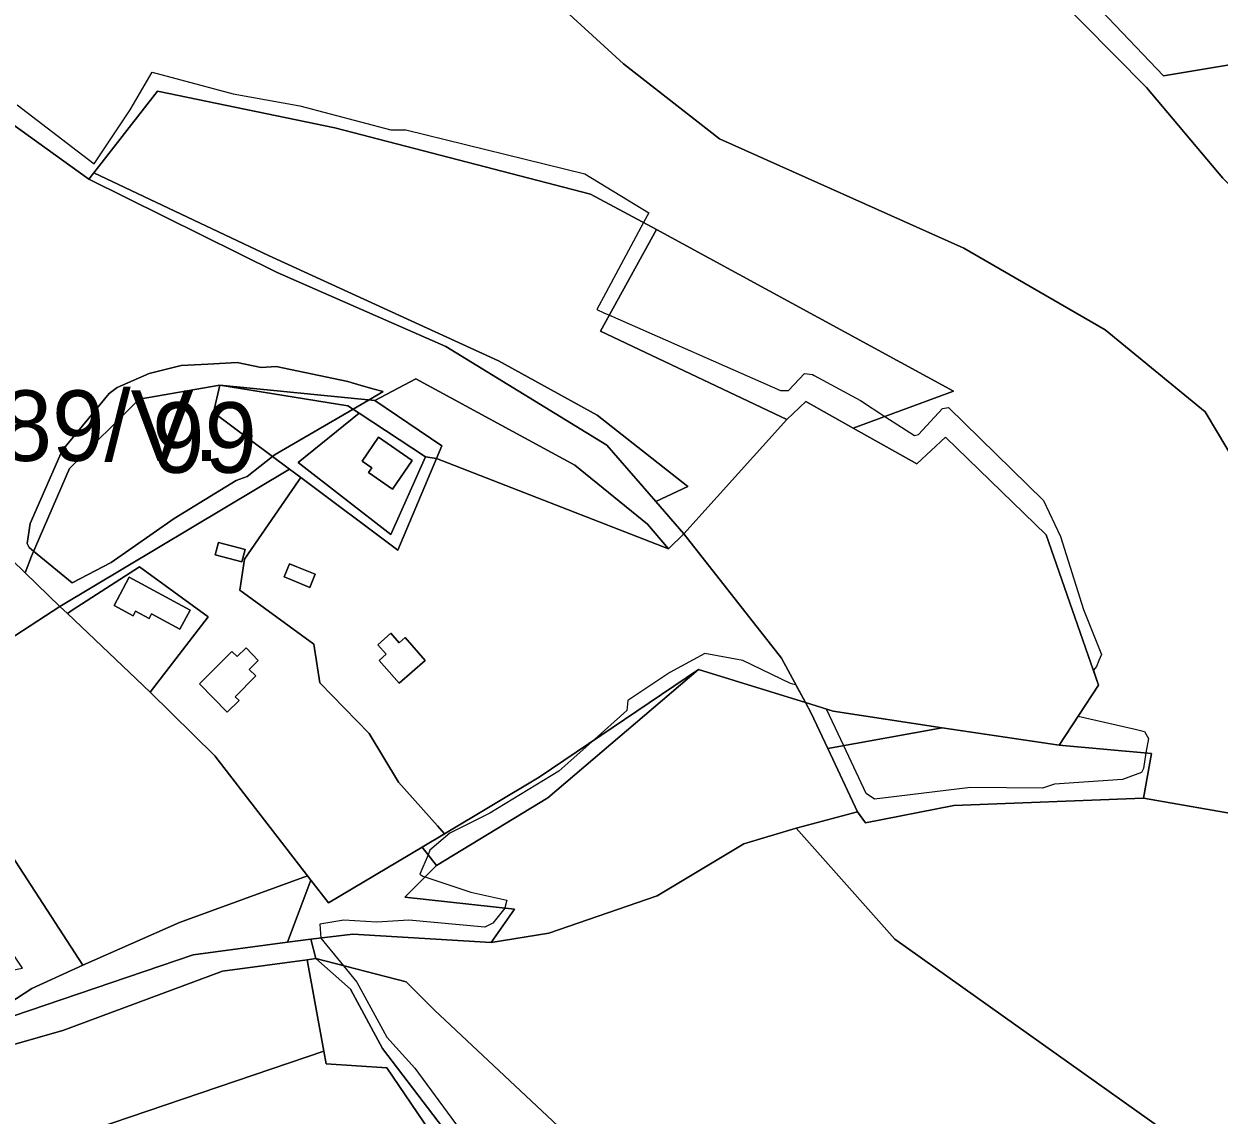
# Model space of a CAD drawing. Extents: x -477304 to -465429, y -1159113 to -1149210.
# Drawn here: x -474554.2 to -474299.9, y -1154850.7 to -1154618.5 of the extents above; entities that cross this region are included whole.
import ezdxf

# ---------------------------------------------------------------- set-up
doc = ezdxf.new("R2010")
doc.units = 0
for name, color, linetype in [('BPEJ_s', 7, 'Continuous'), ('orna_s', 7, 'Continuous'), ('ostatni_s', 7, 'Continuous'), ('PUPFL_s', 7, 'Continuous'), ('trav_porost_s', 7, 'Continuous')]:
    doc.layers.add(name, color=color, linetype=linetype)

msp = doc.modelspace()

# ---------------------------------------------------------------- linework, layer by layer
at = {"layer": 'BPEJ_s'}
for points in [[(-474555.64, -1154635.72), (-474542.89, -1154645.5), (-474539.27, -1154648.27), (-474531.61, -1154636.78), (-474526.9, -1154628.75), (-474509.71, -1154633.38), (-474495.47, -1154635.93), (-474476.12, -1154641.03), (-474472.93, -1154641.03), (-474434.86, -1154650.39), (-474421.26, -1154658.68), (-474422.37, -1154660.75), (-474430.4, -1154675.69), (-474432.3, -1154679.29), (-474430.81, -1154679.95), (-474429.64, -1154680.47), (-474393.19, -1154696.53), (-474391.49, -1154696.53), (-474388.08, -1154692.91), (-474386.38, -1154693.13), (-474386.06, -1154693.31), (-474376.18, -1154698.66), (-474370.99, -1154702.02), (-474364.69, -1154706.1), (-474363.84, -1154705.89), (-474358.74, -1154700.36), (-474357.49, -1154700.15), (-474337.26, -1154719.92), (-474333.65, -1154727.57), (-474328.76, -1154743.1), (-474324.93, -1154752.67), (-474325.47, -1154753.96), (-474326, -1154755.22), (-474326.64, -1154756.04), (-474325.53, -1154759.22), (-474329.87, -1154765.8), (-474317.73, -1154768.59), (-474315.79, -1154769.04), (-474314.94, -1154770.53), (-474315.46, -1154773.64), (-474316, -1154776.91), (-474316.42, -1154777.76), (-474320.46, -1154779.25), (-474334.92, -1154780.31), (-474337.48, -1154781.16), (-474352.79, -1154780.95), (-474373.2, -1154783.5), (-474374.99, -1154782.29), (-474379.78, -1154772.1), (-474383.45, -1154764.29), (-474387.91, -1154762.92), (-474389.97, -1154759.12), (-474390.57, -1154758.96)], [(-474555.64, -1154635.72), (-474542.89, -1154645.5), (-474539.27, -1154648.27), (-474531.61, -1154636.78), (-474526.9, -1154628.75), (-474509.71, -1154633.38), (-474495.47, -1154635.93), (-474476.12, -1154641.03), (-474472.93, -1154641.03), (-474434.86, -1154650.39), (-474421.26, -1154658.68), (-474422.37, -1154660.75), (-474430.4, -1154675.69), (-474432.3, -1154679.29), (-474430.81, -1154679.95), (-474429.64, -1154680.47), (-474393.19, -1154696.53), (-474391.49, -1154696.53), (-474388.08, -1154692.91), (-474386.38, -1154693.13), (-474386.06, -1154693.31), (-474376.18, -1154698.66), (-474370.99, -1154702.02), (-474364.69, -1154706.1), (-474363.84, -1154705.89), (-474358.74, -1154700.36), (-474357.49, -1154700.15), (-474337.26, -1154719.92), (-474333.65, -1154727.57), (-474328.76, -1154743.1), (-474324.93, -1154752.67), (-474325.47, -1154753.96), (-474326, -1154755.22), (-474326.64, -1154756.04), (-474325.53, -1154759.22), (-474329.87, -1154765.8), (-474317.73, -1154768.59), (-474315.79, -1154769.04), (-474314.94, -1154770.53), (-474315.46, -1154773.64), (-474316, -1154776.91), (-474316.42, -1154777.76), (-474320.46, -1154779.25), (-474334.92, -1154780.31), (-474337.48, -1154781.16), (-474352.79, -1154780.95), (-474373.2, -1154783.5), (-474374.99, -1154782.29), (-474379.78, -1154772.1), (-474383.45, -1154764.29), (-474387.91, -1154762.92), (-474389.97, -1154759.12), (-474390.57, -1154758.96), (-474391.06, -1154758.83), (-474401.27, -1154753.94), (-474409.35, -1154752.45), (-474416.79, -1154756.49), (-474425.72, -1154762.45), (-474425.93, -1154764.57), (-474433.38, -1154771.26), (-474440.39, -1154777.54), (-474455.07, -1154786.48), (-474463.57, -1154790.73), (-474467.82, -1154794.34), (-474468.21, -1154795.28), (-474469.95, -1154799.45), (-474469.31, -1154799.87), (-474468.87, -1154800.02), (-474459.1, -1154803.27), (-474451.45, -1154804.97), (-474451.86, -1154806.62), (-474451.87, -1154806.68), (-474454.43, -1154809.87), (-474456.13, -1154810.72), (-474472.29, -1154809.23), (-474479.09, -1154809.65), (-474486.11, -1154809.23), (-474491.21, -1154810.08), (-474491, -1154813.03), (-474486.2, -1154818.92), (-474483.35, -1154822.41), (-474476.97, -1154834.11), (-474471.01, -1154840.7), (-474458.04, -1154858.35)], [(-474390.57, -1154758.96), (-474391.06, -1154758.83), (-474401.27, -1154753.94), (-474409.35, -1154752.45), (-474416.79, -1154756.49), (-474425.72, -1154762.45), (-474425.93, -1154764.57), (-474433.38, -1154771.26), (-474440.39, -1154777.54), (-474455.07, -1154786.48), (-474463.57, -1154790.73), (-474467.82, -1154794.34), (-474468.21, -1154795.28), (-474469.95, -1154799.45), (-474469.31, -1154799.87), (-474468.87, -1154800.02), (-474459.1, -1154803.27), (-474451.45, -1154804.97), (-474451.86, -1154806.62), (-474451.87, -1154806.68), (-474454.43, -1154809.87), (-474456.13, -1154810.72), (-474472.29, -1154809.23), (-474479.09, -1154809.65), (-474486.11, -1154809.23), (-474491.21, -1154810.08), (-474491, -1154813.03), (-474486.2, -1154818.92), (-474483.35, -1154822.41), (-474476.97, -1154834.11), (-474471.01, -1154840.7), (-474458.04, -1154858.35)]]:
    msp.add_lwpolyline(points, dxfattribs=at)
for points in [[(-474508.86, -1154690.58), (-474503.76, -1154691.64), (-474500.57, -1154691.43), (-474485.26, -1154694.62), (-474484.37, -1154694.88), (-474483.13, -1154695.25), (-474479.97, -1154696.13), (-474477.75, -1154696.75), (-474480.77, -1154698.51), (-474484.18, -1154700.49), (-474500.78, -1154710.14), (-474501.31, -1154710.55), (-474506.74, -1154714.82), (-474509.08, -1154715.67), (-474522.26, -1154723.75), (-474535.66, -1154733.1), (-474543.96, -1154737.44), (-474552.16, -1154730.68), (-474553.09, -1154729.91), (-474553.52, -1154729.06), (-474552.88, -1154724.81), (-474546.07, -1154709.29), (-474536.08, -1154697.17), (-474534.38, -1154695.89), (-474527.58, -1154692.91), (-474520.77, -1154691.21), (-474515.05, -1154690.91)], [(-474508.86, -1154690.58), (-474515.05, -1154690.91), (-474520.77, -1154691.21), (-474527.58, -1154692.91), (-474534.38, -1154695.89), (-474536.08, -1154697.17), (-474546.07, -1154709.29), (-474552.88, -1154724.81), (-474553.52, -1154729.06), (-474553.09, -1154729.91), (-474552.16, -1154730.68), (-474543.96, -1154737.44), (-474535.66, -1154733.1), (-474522.26, -1154723.75), (-474509.08, -1154715.67), (-474506.74, -1154714.82), (-474501.31, -1154710.55), (-474500.78, -1154710.14), (-474484.18, -1154700.49), (-474480.77, -1154698.51), (-474477.75, -1154696.75), (-474479.97, -1154696.13), (-474483.13, -1154695.25), (-474484.37, -1154694.88), (-474485.26, -1154694.62), (-474500.57, -1154691.43), (-474503.76, -1154691.64)]]:
    msp.add_lwpolyline(points, close=True, dxfattribs=at)
at = {"layer": 'orna_s'}
msp.add_lwpolyline([(-474541.68, -1154818.78), (-474577.98, -1154762.93), (-474546.55, -1154742.45), (-474544.93, -1154743.93), (-474527.32, -1154760.69), (-474513.56, -1154774.25), (-474493.86, -1154799.79), (-474521.14, -1154809.72)], close=True, dxfattribs=at)
at = {"layer": 'ostatni_s'}
for points in [[(-474500.33, -1154671.41), (-474540.4, -1154651.54), (-474539.37, -1154650.22), (-474502.17, -1154667.8), (-474453.2, -1154690.19), (-474432.2, -1154701.74), (-474412.91, -1154716.9), (-474419.75, -1154720.15), (-474430.19, -1154708.17), (-474464.4, -1154687.15)], [(-474546.55, -1154742.45), (-474553.94, -1154735.28), (-474552.63, -1154731.76), (-474544.49, -1154713.13), (-474529.72, -1154698.35), (-474512.5, -1154695.38), (-474513.86, -1154701.16), (-474497.68, -1154713.27)], [(-474513.86, -1154701.16), (-474512.5, -1154695.38), (-474485.26, -1154699.78), (-474482.87, -1154701.35), (-474495.83, -1154711.86), (-474476.14, -1154727.17), (-474468.78, -1154710.6), (-474466.41, -1154711.01), (-474474.63, -1154730.51), (-474495.32, -1154715.03), (-474497.68, -1154713.27)], [(-474485.26, -1154699.78), (-474512.5, -1154695.38), (-474479.51, -1154698.63), (-474465.27, -1154708.28), (-474466.41, -1154711.01), (-474468.78, -1154710.6), (-474482.87, -1154701.35)], [(-474482.87, -1154701.35), (-474468.78, -1154710.6), (-474476.14, -1154727.17), (-474495.83, -1154711.86)], [(-474480.88, -1154713.97), (-474480.19, -1154712.97), (-474482.26, -1154711.56), (-474478.78, -1154706.47), (-474471.6, -1154711.38), (-474475.76, -1154717.47)], [(-474480.19, -1154712.97), (-474480.88, -1154713.97), (-474475.76, -1154717.47), (-474471.6, -1154711.38), (-474478.78, -1154706.47), (-474482.26, -1154711.56)], [(-474495.32, -1154715.03), (-474474.63, -1154730.51), (-474466.41, -1154711.01), (-474417.06, -1154730.17), (-474413.77, -1154727.01), (-474393.02, -1154753.48), (-474387.91, -1154762.92), (-474410.7, -1154755.89), (-474444.55, -1154778.82), (-474464.71, -1154790.86), (-474466.23, -1154789.15), (-474474.52, -1154779.84), (-474480.74, -1154769.49), (-474491.24, -1154758.69), (-474492.55, -1154750.45), (-474508.3, -1154738.96), (-474507.31, -1154732.39), (-474495.81, -1154715.73)], [(-474544.93, -1154743.93), (-474546.55, -1154742.45), (-474497.68, -1154713.27), (-474495.32, -1154715.03), (-474495.81, -1154715.73), (-474507.31, -1154732.39), (-474508.3, -1154738.96), (-474492.55, -1154750.45), (-474491.24, -1154758.69), (-474480.74, -1154769.49), (-474474.52, -1154779.84), (-474466.23, -1154789.15), (-474464.71, -1154790.86), (-474469.46, -1154793.7), (-474489.41, -1154805.56), (-474493.15, -1154800.71), (-474493.86, -1154799.79), (-474513.56, -1154774.25), (-474527.32, -1154760.69), (-474515.04, -1154744.67), (-474529.63, -1154734.05), (-474543.97, -1154743.22)], [(-474507.14, -1154730.34), (-474507.83, -1154732.96), (-474513.53, -1154731.45), (-474512.84, -1154728.84)], [(-474513.53, -1154731.45), (-474507.83, -1154732.96), (-474507.14, -1154730.34), (-474512.84, -1154728.84)], [(-474529.63, -1154734.05), (-474515.04, -1154744.67), (-474527.32, -1154760.69), (-474544.93, -1154743.93), (-474543.97, -1154743.22)], [(-474497.26, -1154736.82), (-474498.84, -1154736.19), (-474497.72, -1154733.4), (-474496.14, -1154734.03), (-474492.24, -1154735.6), (-474493.36, -1154738.39)], [(-474497.72, -1154733.4), (-474498.84, -1154736.19), (-474497.26, -1154736.82), (-474493.36, -1154738.39), (-474492.24, -1154735.6), (-474496.14, -1154734.03)], [(-474535.04, -1154742.24), (-474531.8, -1154736.26), (-474518.85, -1154743.22), (-474521.03, -1154747.27), (-474527.04, -1154744.04), (-474527.56, -1154745.01), (-474530.46, -1154743.45), (-474530.98, -1154744.42)], [(-474530.46, -1154743.45), (-474527.56, -1154745.01), (-474527.04, -1154744.04), (-474521.03, -1154747.27), (-474518.85, -1154743.22), (-474531.8, -1154736.26), (-474535.04, -1154742.24), (-474530.98, -1154744.42)], [(-474474.39, -1154758.8), (-474478.63, -1154753.95), (-474477.12, -1154752.64), (-474478.9, -1154750.6), (-474476.12, -1154748.17), (-474474.34, -1154750.2), (-474473.06, -1154749.08), (-474468.82, -1154753.93)], [(-474478.63, -1154753.95), (-474474.39, -1154758.8), (-474468.82, -1154753.93), (-474473.06, -1154749.08), (-474474.34, -1154750.2), (-474476.12, -1154748.17), (-474478.9, -1154750.6), (-474477.12, -1154752.64)], [(-474504.36, -1154753.93), (-474506.26, -1154755.84), (-474504.84, -1154757.25), (-474509.25, -1154761.68), (-474508.44, -1154762.5), (-474510.93, -1154764.96), (-474516.86, -1154758.95), (-474509.94, -1154752.01), (-474508.81, -1154753.14), (-474506.9, -1154751.23)], [(-474516.86, -1154758.95), (-474510.93, -1154764.96), (-474508.44, -1154762.5), (-474509.25, -1154761.68), (-474504.84, -1154757.25), (-474506.26, -1154755.84), (-474504.36, -1154753.93), (-474506.9, -1154751.23), (-474508.81, -1154753.14), (-474509.94, -1154752.01)], [(-474466.41, -1154797.55), (-474469.46, -1154793.7), (-474464.71, -1154790.86), (-474444.55, -1154778.82), (-474410.7, -1154755.89), (-474442.72, -1154783.21)], [(-474383.15, -1154772.71), (-474386.7, -1154765.15), (-474387.91, -1154762.92), (-474382, -1154764.74), (-474358.82, -1154768.29)], [(-474469.46, -1154793.7), (-474466.41, -1154797.55), (-474473.19, -1154804.35), (-474449.84, -1154806.84), (-474454.76, -1154813.98), (-474484.24, -1154812.22), (-474493.19, -1154813.28), (-474498.13, -1154813.93), (-474493.15, -1154800.71), (-474489.41, -1154805.56)], [(-474611.02, -1154822.52), (-474611.64, -1154804.51), (-474604.67, -1154817.65), (-474594.07, -1154826.96), (-474579.2, -1154832.67), (-474567.08, -1154833.17), (-474518.19, -1154816.58), (-474498.13, -1154813.93), (-474493.19, -1154813.28), (-474492.08, -1154817.4), (-474493.97, -1154817.66), (-474511.93, -1154820.1), (-474545.95, -1154832.68), (-474563.17, -1154837.58), (-474579.09, -1154839.11), (-474594.59, -1154833.69), (-474595.46, -1154834.53), (-474597.74, -1154831.78)]]:
    msp.add_lwpolyline(points, close=True, dxfattribs=at)
at = {"layer": 'PUPFL_s'}
for points in [[(-474577.43, -1154608.26), (-474534.34, -1154591.42), (-474528.72, -1154588.6), (-474500.82, -1154575.85), (-474485.61, -1154561.49), (-474488.13, -1154538.93), (-474478.72, -1154537.37), (-474480.67, -1154521.18), (-474481.56, -1154512.48), (-474495.05, -1154471.02), (-474504.41, -1154455.05), (-474503.73, -1154426.92), (-474495.21, -1154459.11), (-474477.34, -1154510.48), (-474456.25, -1154595.84), (-474445.57, -1154609.62), (-474426.63, -1154626.96), (-474406.19, -1154642.93), (-474354.19, -1154666.19), (-474324.11, -1154683.59), (-474302.87, -1154701.05), (-474280.25, -1154739.01)], [(-474280.25, -1154739.01), (-474302.87, -1154701.05), (-474324.11, -1154683.59), (-474354.19, -1154666.19), (-474406.19, -1154642.93), (-474426.63, -1154626.96), (-474445.57, -1154609.62), (-474456.25, -1154595.84), (-474477.34, -1154510.48), (-474470.27, -1154508.63), (-474453.72, -1154504.3), (-474449.3, -1154519), (-474448.55, -1154542.83), (-474461.18, -1154546.91), (-474450.51, -1154592.79), (-474430.13, -1154615.88), (-474354.17, -1154582.76), (-474342.6, -1154604.43), (-474315.31, -1154632.03), (-474299.08, -1154651.35)], [(-474294.09, -1154787.08), (-474315.97, -1154783.22), (-474314.26, -1154773.75), (-474333.95, -1154771.98), (-474325.53, -1154759.22), (-474336.7, -1154727.23), (-474358.14, -1154706.45), (-474364.22, -1154712.1), (-474377.76, -1154704.5), (-474356.42, -1154696.68), (-474419.62, -1154662.23), (-474433.63, -1154654.7), (-474488.05, -1154640.58), (-474525.82, -1154632.82), (-474539.37, -1154650.22), (-474540.4, -1154651.54), (-474582.76, -1154621.11)]]:
    msp.add_lwpolyline(points, dxfattribs=at)
for points in [[(-474351.36, -1154576.74), (-474351.54, -1154574.41), (-474269.43, -1154569.99), (-474265.46, -1154587.35), (-474252.7, -1154619.72), (-474311.76, -1154629.58), (-474339.54, -1154600.31)], [(-474198.53, -1154725.73), (-474175.02, -1154779.46), (-474213.57, -1154783.74), (-474224.84, -1154785.28), (-474231.82, -1154755.93), (-474239.21, -1154729.76), (-474250.05, -1154704.22), (-474259.38, -1154689.67), (-474270.18, -1154680.4), (-474299.08, -1154651.35), (-474315.31, -1154632.03), (-474342.6, -1154604.43), (-474354.17, -1154582.76), (-474358.45, -1154574.74), (-474353.84, -1154574.52), (-474351.54, -1154574.41), (-474351.36, -1154576.74), (-474339.54, -1154600.31), (-474311.76, -1154629.58), (-474252.7, -1154619.72), (-474210.79, -1154710.64)], [(-474436.97, -1154712.36), (-474470.79, -1154694.05), (-474479.51, -1154698.63), (-474512.5, -1154695.38), (-474529.72, -1154698.35), (-474544.49, -1154713.13), (-474552.63, -1154731.76), (-474553.94, -1154735.28), (-474579.09, -1154710.9), (-474605.15, -1154684.77), (-474660.51, -1154640.35), (-474610.2, -1154626.53), (-474582.76, -1154621.11), (-474540.4, -1154651.54), (-474500.33, -1154671.41), (-474464.4, -1154687.15), (-474430.19, -1154708.17), (-474419.75, -1154720.15), (-474413.77, -1154727.01), (-474417.06, -1154730.17), (-474421.5, -1154724.95)], [(-474432.2, -1154701.74), (-474453.2, -1154690.19), (-474502.17, -1154667.8), (-474539.37, -1154650.22), (-474525.82, -1154632.82), (-474488.05, -1154640.58), (-474433.63, -1154654.7), (-474419.62, -1154662.23), (-474431.51, -1154683.88), (-474391.84, -1154702.66), (-474413.77, -1154727.01), (-474419.75, -1154720.15), (-474412.91, -1154716.9)], [(-474387.86, -1154698.83), (-474391.84, -1154702.66), (-474431.51, -1154683.88), (-474419.62, -1154662.23), (-474356.42, -1154696.68), (-474377.76, -1154704.5)], [(-474470.79, -1154694.05), (-474436.97, -1154712.36), (-474421.5, -1154724.95), (-474417.06, -1154730.17), (-474466.41, -1154711.01), (-474465.27, -1154708.28), (-474479.51, -1154698.63)], [(-474442.72, -1154783.21), (-474410.7, -1154755.89), (-474387.91, -1154762.92), (-474386.7, -1154765.15), (-474383.15, -1154772.71), (-474376.84, -1154786.16), (-474389.88, -1154789.65), (-474401.02, -1154792.98), (-474419.5, -1154804.03), (-474442.51, -1154811.97), (-474454.76, -1154813.98), (-474449.84, -1154806.84), (-474473.19, -1154804.35), (-474466.41, -1154797.55)], [(-474383.15, -1154772.71), (-474358.82, -1154768.29), (-474333.95, -1154771.98), (-474314.26, -1154773.75), (-474315.97, -1154783.22), (-474356.36, -1154784.82), (-474375.12, -1154788.52), (-474376.84, -1154786.16)], [(-474226.51, -1154811.13), (-474240.72, -1154830.19), (-474251.42, -1154840.56), (-474260.03, -1154845.61), (-474271.08, -1154856.86), (-474288.93, -1154870.04), (-474368.88, -1154813.26), (-474389.88, -1154789.65), (-474376.84, -1154786.16), (-474375.12, -1154788.52), (-474356.36, -1154784.82), (-474315.97, -1154783.22), (-474294.09, -1154787.08), (-474272.8, -1154788.07), (-474243.8, -1154787.71), (-474224.84, -1154785.28), (-474213.57, -1154783.74), (-474220.92, -1154798.92)], [(-474401.02, -1154792.98), (-474389.88, -1154789.65), (-474368.88, -1154813.26), (-474288.93, -1154870.04), (-474151.26, -1154918.1), (-474196.87, -1155060.27), (-474423.82, -1154897.05), (-474437.12, -1154856.24), (-474466.83, -1154828.36), (-474472.89, -1154822.37), (-474492.08, -1154817.4), (-474493.19, -1154813.28), (-474484.24, -1154812.22), (-474454.76, -1154813.98), (-474442.51, -1154811.97), (-474419.5, -1154804.03)], [(-474456.47, -1154864.64), (-474444.82, -1154893.23), (-474467.62, -1154898.45), (-474472.98, -1154879.42), (-474468.1, -1154875.48), (-474464.99, -1154873.25), (-474461.41, -1154863.6), (-474477.02, -1154840.64), (-474489.89, -1154839.81), (-474490.4, -1154837.09), (-474493.97, -1154817.66), (-474492.08, -1154817.4), (-474484.7, -1154823.93), (-474477.92, -1154836.55)], [(-474436.48, -1154924.53), (-474444.82, -1154893.23), (-474456.47, -1154864.64), (-474477.92, -1154836.55), (-474484.7, -1154823.93), (-474492.08, -1154817.4), (-474472.89, -1154822.37), (-474466.83, -1154828.36), (-474437.12, -1154856.24), (-474423.82, -1154897.05), (-474196.87, -1155060.27), (-474201.31, -1155074.1), (-474255.55, -1155070.01), (-474304.79, -1155064.57), (-474345.32, -1155059.02), (-474389.27, -1155021.62), (-474408.45, -1155002.52), (-474423.87, -1154975.99), (-474435.93, -1154948.81), (-474436.08, -1154942.31), (-474436.19, -1154937.53)]]:
    msp.add_lwpolyline(points, close=True, dxfattribs=at)
at = {"layer": 'trav_porost_s'}
for points in [[(-474577.98, -1154762.93), (-474587.6, -1154769.75), (-474617.78, -1154788.89), (-474632.51, -1154764.4), (-474646.53, -1154752.94), (-474658.54, -1154740.25), (-474640.74, -1154716.19), (-474634.91, -1154708.32), (-474618.83, -1154693.22), (-474610.01, -1154687.78), (-474606.68, -1154685.72), (-474605.15, -1154684.77), (-474579.09, -1154710.9), (-474553.94, -1154735.28), (-474546.55, -1154742.45)], [(-474413.77, -1154727.01), (-474391.84, -1154702.66), (-474387.86, -1154698.83), (-474377.76, -1154704.5), (-474364.22, -1154712.1), (-474358.14, -1154706.45), (-474336.7, -1154727.23), (-474325.53, -1154759.22), (-474333.95, -1154771.98), (-474358.82, -1154768.29), (-474382, -1154764.74), (-474387.91, -1154762.92), (-474393.02, -1154753.48)], [(-474587.6, -1154769.75), (-474577.98, -1154762.93), (-474541.68, -1154818.78), (-474552.5, -1154823.74), (-474567.08, -1154833.17), (-474579.2, -1154832.67), (-474594.07, -1154826.96), (-474554.49, -1154819.43)], [(-474518.19, -1154816.58), (-474567.08, -1154833.17), (-474552.5, -1154823.74), (-474541.68, -1154818.78), (-474521.14, -1154809.72), (-474493.86, -1154799.79), (-474493.15, -1154800.71), (-474498.13, -1154813.93)], [(-474591.24, -1154838.38), (-474595.46, -1154834.53), (-474594.59, -1154833.69), (-474579.09, -1154839.11), (-474563.17, -1154837.58), (-474545.95, -1154832.68), (-474511.93, -1154820.1), (-474493.97, -1154817.66), (-474490.4, -1154837.09), (-474546.56, -1154856.2), (-474562.1, -1154867.34), (-474575.64, -1154854.29)], [(-474471.63, -1154875.43), (-474524.94, -1154891.7), (-474545.33, -1154890.58), (-474549.35, -1154885.54), (-474533.27, -1154872.67), (-474546.56, -1154856.2), (-474490.4, -1154837.09), (-474489.89, -1154839.81), (-474477.02, -1154840.64), (-474461.41, -1154863.6), (-474464.99, -1154873.25), (-474468.1, -1154875.48)]]:
    msp.add_lwpolyline(points, close=True, dxfattribs=at)

# ---------------------------------------------------------------- texts
at = {"layer": 'BPEJ_s'}
for s, p in [('84189/V.', (-474592.85, -1154711.49)), ('99', (-474526.93, -1154714.01))]:
    msp.add_text(s, height=15, dxfattribs=at).set_placement(p)

doc.saveas('drawing.dxf')
